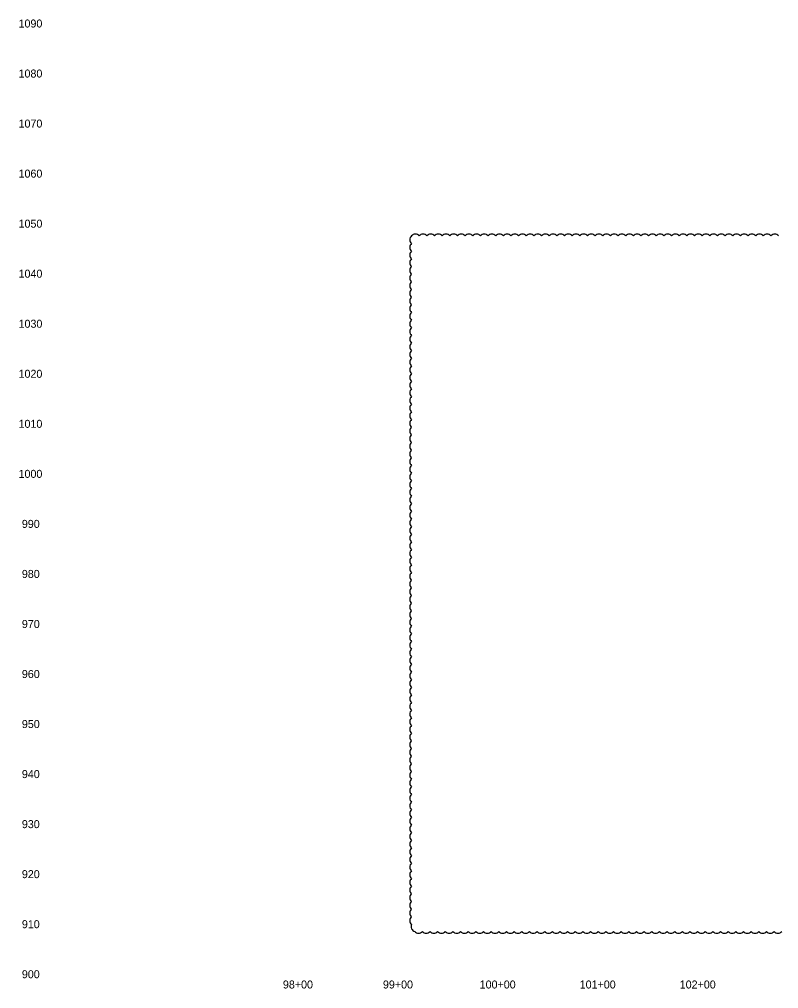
# Model space of a CAD drawing. Extents: x 16972803 to 16974463, y 12564277 to 12565299.
# Drawn here: x 16972803 to 16973562, y 12564277 to 12565246 of the extents above; entities that cross this region are included whole.
import ezdxf

# ---------------------------------------------------------------- set-up
doc = ezdxf.new("R2010")
doc.units = 0
for name, color, linetype in [('RD_DDB_ElevTX', 7, 'Continuous'), ('RD_DDB_StaTX', 7, 'Continuous'), ('RD_SHT_TX', 7, 'Continuous')]:
    doc.layers.add(name, color=color, linetype=linetype)

msp = doc.modelspace()

# ---------------------------------------------------------------- linework, layer by layer
at = {"layer": 'RD_SHT_TX'}
for centre, start, end in [((16973198.69, 12565025.7), 130, 230), ((16973199.31, 12565026.32), 40, 140), ((16973206.95, 12565026.32), 40, 140), ((16973214.6, 12565026.32), 40, 140), ((16973222.24, 12565026.32), 40, 140), ((16973229.89, 12565026.32), 40, 140), ((16973237.53, 12565026.32), 40, 140), ((16973245.18, 12565026.32), 40, 140), ((16973252.82, 12565026.32), 40, 140), ((16973260.47, 12565026.32), 40, 140), ((16973268.11, 12565026.32), 40, 140), ((16973275.75, 12565026.32), 40, 140), ((16973283.4, 12565026.32), 40, 140), ((16973291.04, 12565026.32), 40, 140), ((16973298.69, 12565026.32), 40, 140), ((16973306.33, 12565026.32), 40, 140), ((16973313.98, 12565026.32), 40, 140), ((16973321.62, 12565026.32), 40, 140), ((16973329.27, 12565026.32), 40, 140), ((16973336.91, 12565026.32), 40, 140), ((16973344.56, 12565026.32), 40, 140), ((16973352.2, 12565026.32), 40, 140), ((16973359.85, 12565026.32), 40, 140), ((16973367.49, 12565026.32), 40, 140), ((16973375.13, 12565026.32), 40, 140), ((16973382.78, 12565026.32), 40, 140), ((16973390.42, 12565026.32), 40, 140), ((16973398.07, 12565026.32), 40, 140), ((16973405.71, 12565026.32), 40, 140), ((16973413.36, 12565026.32), 40, 140), ((16973421, 12565026.32), 40, 140), ((16973428.65, 12565026.32), 40, 140), ((16973436.29, 12565026.32), 40, 140), ((16973443.94, 12565026.32), 40, 140), ((16973451.58, 12565026.32), 40, 140), ((16973459.22, 12565026.32), 40, 140), ((16973466.87, 12565026.32), 40, 140), ((16973474.51, 12565026.32), 40, 140), ((16973482.16, 12565026.32), 40, 140), ((16973489.8, 12565026.32), 40, 140), ((16973497.45, 12565026.32), 40, 140), ((16973505.09, 12565026.32), 40, 140), ((16973512.74, 12565026.32), 40, 140), ((16973520.38, 12565026.32), 40, 140), ((16973528.03, 12565026.32), 40, 140), ((16973535.67, 12565026.32), 40, 140), ((16973543.31, 12565026.32), 40, 140), ((16973550.96, 12565026.32), 40, 140), ((16973558.6, 12565026.32), 40, 140), ((16973198.69, 12565018.06), 130, 230), ((16973198.69, 12565010.41), 130, 230), ((16973198.69, 12565002.77), 130, 230), ((16973198.69, 12564995.12), 130, 230), ((16973198.69, 12564987.48), 130, 230), ((16973198.69, 12564979.83), 130, 230), ((16973198.69, 12564972.19), 130, 230), ((16973198.69, 12564964.54), 130, 230), ((16973198.69, 12564956.9), 130, 230), ((16973198.69, 12564949.26), 130, 230), ((16973198.69, 12564941.61), 130, 230), ((16973198.69, 12564933.97), 130, 230), ((16973198.69, 12564926.32), 130, 230), ((16973198.69, 12564918.68), 130, 230), ((16973198.69, 12564911.03), 130, 230), ((16973198.69, 12564903.39), 130, 230), ((16973198.69, 12564895.74), 130, 230), ((16973198.69, 12564888.1), 130, 230), ((16973198.69, 12564880.45), 130, 230), ((16973198.69, 12564872.81), 130, 230), ((16973198.69, 12564865.16), 130, 230), ((16973198.69, 12564857.52), 130, 230), ((16973198.69, 12564849.88), 130, 230), ((16973198.69, 12564842.23), 130, 230), ((16973198.69, 12564834.59), 130, 230), ((16973198.69, 12564826.94), 130, 230), ((16973198.69, 12564819.3), 130, 230), ((16973198.69, 12564811.65), 130, 230), ((16973198.69, 12564804.01), 130, 230), ((16973198.69, 12564796.36), 130, 230), ((16973198.69, 12564788.72), 130, 230), ((16973198.69, 12564781.07), 130, 230), ((16973198.69, 12564773.43), 130, 230), ((16973198.69, 12564765.79), 130, 230), ((16973198.69, 12564758.14), 130, 230), ((16973198.69, 12564750.5), 130, 230), ((16973198.69, 12564742.85), 130, 230), ((16973198.69, 12564735.21), 130, 230), ((16973198.69, 12564727.56), 130, 230), ((16973198.69, 12564719.92), 130, 230), ((16973198.69, 12564712.27), 130, 230), ((16973198.69, 12564704.63), 130, 230), ((16973198.69, 12564696.98), 130, 230), ((16973198.69, 12564689.34), 130, 230), ((16973198.69, 12564681.7), 130, 230), ((16973198.69, 12564674.05), 130, 230), ((16973198.69, 12564666.41), 130, 230), ((16973198.69, 12564658.76), 130, 230), ((16973198.69, 12564651.12), 130, 230), ((16973198.69, 12564643.47), 130, 230), ((16973198.69, 12564635.83), 130, 230), ((16973198.69, 12564628.18), 130, 230), ((16973198.69, 12564620.54), 130, 230), ((16973198.69, 12564612.89), 130, 230), ((16973198.69, 12564605.25), 130, 230), ((16973198.69, 12564597.6), 130, 230), ((16973198.69, 12564589.96), 130, 230), ((16973198.69, 12564582.32), 130, 230), ((16973198.69, 12564574.67), 130, 230), ((16973198.69, 12564567.03), 130, 230), ((16973198.69, 12564559.38), 130, 230), ((16973198.69, 12564551.74), 130, 230), ((16973198.69, 12564544.09), 130, 230), ((16973198.69, 12564536.45), 130, 230), ((16973198.69, 12564528.8), 130, 230), ((16973198.69, 12564521.16), 130, 230), ((16973198.69, 12564513.51), 130, 230), ((16973198.69, 12564505.87), 130, 230), ((16973198.69, 12564498.23), 130, 230), ((16973198.69, 12564490.58), 130, 230), ((16973198.69, 12564482.94), 130, 230), ((16973198.69, 12564475.29), 130, 230), ((16973198.69, 12564467.65), 130, 230), ((16973198.69, 12564460), 130, 230), ((16973198.69, 12564452.36), 130, 230), ((16973198.69, 12564444.71), 130, 230), ((16973198.69, 12564437.07), 130, 230), ((16973198.69, 12564429.42), 130, 230), ((16973198.69, 12564421.78), 130, 230), ((16973198.69, 12564414.14), 130, 230), ((16973198.69, 12564406.49), 130, 230), ((16973198.69, 12564398.85), 130, 230), ((16973198.69, 12564391.2), 130, 230), ((16973198.69, 12564383.56), 130, 230), ((16973198.69, 12564375.91), 130, 230), ((16973198.69, 12564368.27), 130, 230), ((16973198.69, 12564360.62), 130, 230), ((16973198.69, 12564352.98), 130, 230), ((16973198.69, 12564345.33), 130, 230), ((16973199.97, 12564339.33), 154.10759, 254.10759), ((16973202.43, 12564337.74), 220, 320), ((16973210.08, 12564337.74), 220, 320), ((16973217.72, 12564337.74), 220, 320), ((16973225.36, 12564337.74), 220, 320), ((16973233.01, 12564337.74), 220, 320), ((16973240.65, 12564337.74), 220, 320), ((16973248.3, 12564337.74), 220, 320), ((16973255.94, 12564337.74), 220, 320), ((16973263.59, 12564337.74), 220, 320), ((16973271.23, 12564337.74), 220, 320), ((16973278.88, 12564337.74), 220, 320), ((16973286.52, 12564337.74), 220, 320), ((16973294.17, 12564337.74), 220, 320), ((16973301.81, 12564337.74), 220, 320), ((16973309.45, 12564337.74), 220, 320), ((16973317.1, 12564337.74), 220, 320), ((16973324.74, 12564337.74), 220, 320), ((16973332.39, 12564337.74), 220, 320), ((16973340.03, 12564337.74), 220, 320), ((16973347.68, 12564337.74), 220, 320), ((16973355.32, 12564337.74), 220, 320), ((16973362.97, 12564337.74), 220, 320), ((16973370.61, 12564337.74), 220, 320), ((16973378.26, 12564337.74), 220, 320), ((16973385.9, 12564337.74), 220, 320), ((16973393.55, 12564337.74), 220, 320), ((16973401.19, 12564337.74), 220, 320), ((16973408.83, 12564337.74), 220, 320), ((16973416.48, 12564337.74), 220, 320), ((16973424.12, 12564337.74), 220, 320), ((16973431.77, 12564337.74), 220, 320), ((16973439.41, 12564337.74), 220, 320), ((16973447.06, 12564337.74), 220, 320), ((16973454.7, 12564337.74), 220, 320), ((16973462.35, 12564337.74), 220, 320), ((16973469.99, 12564337.74), 220, 320), ((16973477.64, 12564337.74), 220, 320), ((16973485.28, 12564337.74), 220, 320), ((16973492.92, 12564337.74), 220, 320), ((16973500.57, 12564337.74), 220, 320), ((16973508.21, 12564337.74), 220, 320), ((16973515.86, 12564337.74), 220, 320), ((16973523.5, 12564337.74), 220, 320), ((16973531.15, 12564337.74), 220, 320), ((16973538.79, 12564337.74), 220, 320), ((16973546.44, 12564337.74), 220, 320), ((16973554.08, 12564337.74), 220, 320), ((16973561.73, 12564337.74), 220, 320)]:
    msp.add_arc(centre, 4.99, start, end, dxfattribs=at)

# ---------------------------------------------------------------- texts
at = {"layer": 'RD_DDB_ElevTX'}
for s, p in [('1090', (16972802.55, 12565237.79)), ('1080', (16972802.55, 12565187.79)), ('1070', (16972802.55, 12565137.79)), ('1060', (16972802.55, 12565087.79)), ('1050', (16972802.55, 12565037.79)), ('1040', (16972802.55, 12564987.79)), ('1030', (16972802.55, 12564937.79)), ('1020', (16972802.55, 12564887.79)), ('1010', (16972802.55, 12564837.79)), ('1000', (16972802.55, 12564787.79)), ('990', (16972805.86, 12564737.79)), ('980', (16972805.86, 12564687.79)), ('970', (16972805.86, 12564637.79)), ('960', (16972805.86, 12564587.79)), ('950', (16972805.86, 12564537.79)), ('940', (16972805.86, 12564487.79)), ('930', (16972805.86, 12564437.79)), ('920', (16972805.86, 12564387.79)), ('910', (16972805.86, 12564337.79)), ('900', (16972805.86, 12564287.79))]:
    msp.add_text(s, height=8, dxfattribs=at).set_placement(p)
at = {"layer": 'RD_DDB_StaTX'}
for s, p in [('98+00', (16973066.84, 12564277.54)), ('99+00', (16973166.84, 12564277.54)), ('100+00', (16973263.54, 12564277.54)), ('101+00', (16973363.54, 12564277.54)), ('102+00', (16973463.54, 12564277.54))]:
    msp.add_text(s, height=8, dxfattribs=at).set_placement(p)

doc.saveas('drawing.dxf')
